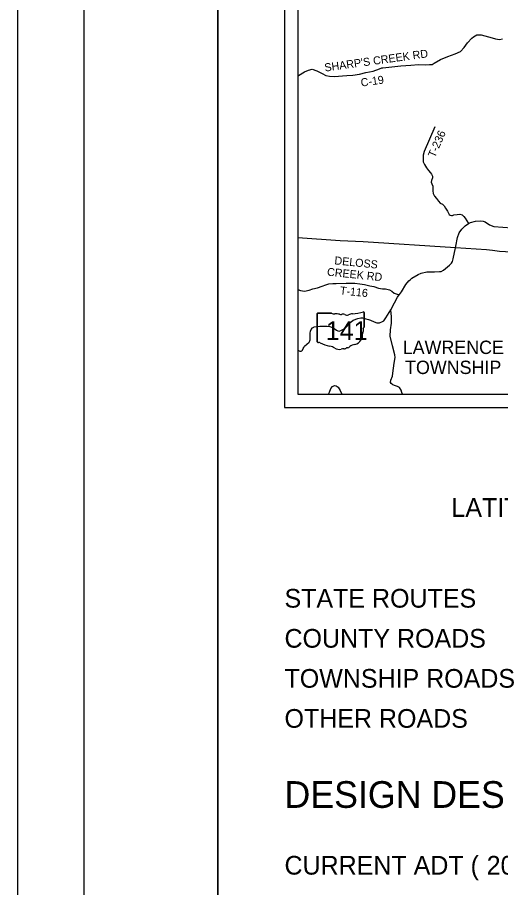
# Model space of a CAD drawing. Extents: x -6.4 to 34, y -1.2 to 22.
# Drawn here: x 0 to 3.62, y 10.4 to 16.92 of the extents above; entities that cross this region are included whole.
import ezdxf

# ---------------------------------------------------------------- set-up
doc = ezdxf.new("R2010")
doc.units = 0
for name, color, linetype in [('GM_X_County', 7, 'Continuous'), ('GM_X_County_ROW', 7, 'Continuous'), ('GM_X_Minor_Lake', 7, 'Continuous'), ('GM_X_Minor_River', 7, 'Continuous'), ('GM_X_Minor_River_Text', 7, 'Continuous'), ('GM_X_Section', 7, 'Continuous'), ('GM_X_Township', 7, 'Continuous'), ('GM_X_Township_Road', 7, 'Continuous'), ('GM_X_Township_ROW', 7, 'Continuous'), ('GM_X_Township_Subdivision', 7, 'Continuous'), ('GM_X_Township_Subdivision_Text', 7, 'Continuous'), ('GM_X_Township_Text', 7, 'Continuous')]:
    doc.layers.add(name, color=color, linetype=linetype)

msp = doc.modelspace()

# ---------------------------------------------------------------- linework, layer by layer
at = {"layer": 'GM_X_County'}
for points in [[(0.5, 21.5), (1.5, 21.5), (1.5, 0.5), (0.5, 0.5)], [(1.5, 21.5), (33.5, 21.5), (33.5, 0.5), (1.5, 0.5)]]:
    msp.add_lwpolyline(points, close=True, dxfattribs=at)
at = {"layer": 'GM_X_County_ROW'}
for p, q in [((2.2455, 14.7029), (2.2455, 14.4903)), ((2.3514, 14.7065), (2.2489, 14.7065)), ((2.5956, 14.6006), (2.5956, 14.7118)), ((2.5955, 14.6006), (2.5956, 14.6006))]:
    msp.add_line(p, q, dxfattribs=at)
for centre, major_axis, start_param, end_param in [((2.2495, 14.7033), (0.00406, 0), 1.712693, 3.28349), ((2.3759, 14.7312), (0.0393, 0), 4.042523, 4.731795), ((2.3889, 14.5872), (0.1412, 0), 1.404758, 1.657858), ((2.421, 14.7044), (0.0113, 0), 3.836095, 5.185415), ((2.4376, 14.6799), (0.0236, 0), 0.950623, 2.079405), ((2.4681, 14.7136), (0.0284, 0), 4.081561, 5.145723), ((2.5182, 14.6416), (0.0747, 0), 1.699011, 2.107814), ((2.4708, 14.9963), (0.3713, 0), 4.814394, 5.042369), ((2.5917, 14.7123), (0.0039, 0), 6.141152, 7.989035), ((2.4916, 14.5399), (0.0929, 0), 5.101752, 6.440018), ((2.6095, 14.5541), (0.0263, 0), 2.387724, 3.262537), ((2.5947, 14.5924), (0.00603, 0), 1.883978, 3.671073), ((2.5563, 14.5784), (0.0362, 0), 5.934695, 6.695948), ((2.5914, 14.6002), (0.00417, 0), 5.05454, 6.418171), ((2.2495, 14.4898), (0.00409, 0), 3.00124, 4.508301), ((2.2501, 14.5116), (0.0312, 0), 4.665946, 4.897461), ((2.2565, 14.478), (0.0113, 0), 0.519207, 1.627899), ((2.3987, 14.669), (0.2681, 0), 4.195997, 4.488961), ((2.3187, 14.3948), (0.0839, 0), 0.823519, 1.323587), ((2.4095, 14.477), (0.0532, 0), 4.026481, 4.996735), ((2.4402, 14.4035), (0.0437, 0), 1.495662, 1.94098), ((2.4441, 14.4611), (0.0284, 0), 4.691044, 5.507374), ((2.4698, 14.4405), (0.00798, 0), 1.147584, 2.315152), ((2.4664, 14.4697), (0.03, 0), 4.937069, 5.64225), ((2.5308, 14.4306), (0.0509, 0), 1.647645, 2.488434)]:
    msp.add_ellipse(centre, major_axis=major_axis, ratio=0.8, start_param=start_param, end_param=end_param, dxfattribs=at)
at = {"layer": 'GM_X_Minor_Lake'}
for points in [[(3.1163, 15.0159), (3.1195, 15.016), (3.1224, 15.0161), (3.16, 15.0171), (3.1737, 15.0188), (3.1901, 15.0273), (3.2345, 15.0644), (3.2498, 15.0801), (3.2571, 15.0918), (3.2627, 15.1137), (3.2794, 15.1952), (3.282, 15.208), (3.2961, 15.273), (3.309, 15.3078), (3.3291, 15.336), (3.3521, 15.3604), (3.3777, 15.3764), (3.3937, 15.3849), (3.4306, 15.3963), (3.4681, 15.3985), (3.487, 15.396), (3.5028, 15.3905), (3.5361, 15.3678), (3.5665, 15.3546), (3.7016, 15.3459)], [(2.9407, 14.9563), (2.9468, 14.9614), (2.9537, 14.9671), (3.0003, 14.9946), (3.0242, 15.005), (3.0656, 15.0144), (3.1163, 15.0159)], [(2.3199, 14.6094), (2.3383, 14.6058), (2.365, 14.5957), (2.3906, 14.5779), (2.4, 14.5729), (2.4083, 14.5705), (2.4209, 14.5753), (2.4312, 14.5813), (2.4548, 14.5943), (2.4629, 14.6018), (2.4813, 14.6235), (2.4989, 14.6412), (2.5138, 14.6524), (2.5489, 14.6649), (2.5728, 14.6707), (2.5849, 14.6717), (2.6098, 14.6646), (2.6283, 14.6587), (2.6449, 14.6528), (2.6709, 14.6415), (2.6913, 14.6333), (2.7106, 14.6342), (2.735, 14.6426), (2.743, 14.649), (2.7592, 14.672), (2.797, 14.7311), (2.8234, 14.7831), (2.8467, 14.8246), (2.8594, 14.8434), (2.8602, 14.8445), (2.8756, 14.8652), (2.9081, 14.9217), (2.9307, 14.948), (2.9407, 14.9563)], [(2.2199, 14.6018), (2.2227, 14.6034), (2.2648, 14.6086), (2.3194, 14.6095), (2.3199, 14.6094)], [(2.1, 14.4284), (2.1088, 14.4237), (2.1159, 14.4202), (2.1243, 14.4201), (2.1304, 14.4231), (2.135, 14.4295), (2.1404, 14.4408), (2.1439, 14.4499), (2.1505, 14.4585), (2.1846, 14.4892), (2.19, 14.4979), (2.1931, 14.507), (2.1933, 14.5218), (2.1918, 14.5552), (2.1943, 14.5718), (2.1993, 14.5839), (2.2086, 14.5956), (2.2199, 14.6018)]]:
    msp.add_lwpolyline(points, dxfattribs=at)
at = {"layer": 'GM_X_Minor_River'}
for points in [[(2.1, 16.4801), (2.106, 16.4873), (2.1497, 16.5143), (2.1801, 16.5264), (2.2075, 16.5328), (2.2428, 16.5218), (2.2826, 16.5009), (2.3096, 16.4872), (2.3373, 16.4804), (2.3723, 16.4796), (2.4661, 16.4864), (2.5109, 16.4887), (2.5618, 16.497), (2.6101, 16.5087), (2.6632, 16.5197), (2.7107, 16.5368), (2.7293, 16.5425), (2.7354, 16.5444), (2.7825, 16.5485), (2.8707, 16.5599), (2.9451, 16.564), (3.0036, 16.5697), (3.053, 16.5659), (3.0853, 16.5681), (3.1058, 16.5693), (3.1213, 16.5784), (3.1685, 16.6068), (3.2232, 16.6277), (3.2779, 16.6482), (3.3189, 16.6671), (3.3452, 16.6964), (3.3699, 16.7302), (3.4037, 16.7658), (3.4163, 16.7761), (3.4398, 16.7905), (3.4732, 16.7901), (3.5553, 16.7688), (3.5789, 16.7622), (3.5952, 16.7587), (3.6096, 16.7552), (3.6327, 16.76)], [(2.883, 14.1), (2.8799, 14.1104), (2.8743, 14.1301), (2.8606, 14.148), (2.8462, 14.1567), (2.8245, 14.1647), (2.812, 14.1689), (2.798, 14.178), (2.7949, 14.1856), (2.7968, 14.2042), (2.8094, 14.2327), (2.8121, 14.2555), (2.8216, 14.3303), (2.8277, 14.374), (2.8255, 14.3942), (2.8092, 14.4614), (2.791, 14.5343), (2.7926, 14.5807), (2.8006, 14.6312), (2.8014, 14.6794), (2.797, 14.7311)]]:
    msp.add_lwpolyline(points, dxfattribs=at)
at = {"layer": 'GM_X_Minor_River_Text'}
for points in [[(3.1247, 16.1013), (3.0448, 15.9165), (3.0391, 15.8896), (3.0375, 15.8592), (3.0379, 15.8391), (3.0478, 15.8189), (3.0633, 15.7954), (3.0796, 15.7749), (3.0933, 15.7574), (3.0997, 15.7471), (3.1081, 15.7316), (3.1092, 15.7202), (3.1016, 15.7004), (3.0982, 15.6875), (3.1042, 15.6754), (3.1099, 15.6575), (3.1114, 15.6233), (3.1125, 15.6032), (3.1224, 15.5835), (3.1383, 15.5645), (3.1535, 15.5447), (3.1668, 15.5295), (3.1841, 15.5221), (3.195, 15.511), (3.2045, 15.4934), (3.2199, 15.47), (3.2342, 15.446), (3.2411, 15.4412), (3.2516, 15.4371), (3.2584, 15.4383), (3.2681, 15.4425), (3.292, 15.4455), (3.3125, 15.4463), (3.33, 15.4421), (3.3437, 15.4299), (3.3524, 15.4182), (3.3777, 15.3764)], [(2.1, 14.8833), (2.1206, 14.8757), (2.1506, 14.8703), (2.1855, 14.879), (2.2125, 14.8874), (2.2475, 14.8965), (2.2816, 14.909), (2.309, 14.9192), (2.3322, 14.9257), (2.3626, 14.928), (2.3861, 14.9287), (2.4617, 14.9302), (2.4955, 14.9309), (2.5263, 14.9309), (2.5646, 14.9256), (2.5999, 14.9195), (2.6398, 14.9111), (2.6702, 14.9054), (2.7051, 14.894), (2.7344, 14.8894), (2.7553, 14.8879), (2.7864, 14.8799), (2.8031, 14.8712), (2.8221, 14.856), (2.8594, 14.8434)], [(2.3288, 14.1), (2.3368, 14.1148), (2.3467, 14.1421), (2.3589, 14.1565), (2.3733, 14.1645), (2.3862, 14.1626), (2.4025, 14.1512), (2.417, 14.1277), (2.4299, 14.1)]]:
    msp.add_lwpolyline(points, dxfattribs=at)
at = {"layer": 'GM_X_Section'}
msp.add_lwpolyline([(0, 0), (34, 0), (34, 22), (0, 22)], close=True, dxfattribs=at)
at = {"layer": 'GM_X_Township'}
for p, q in [((2, 21), (2, 14)), ((2.1, 20.9), (2.1, 14.1)), ((2.1, 14.1), (8.9, 14.1)), ((2, 14), (9, 14))]:
    msp.add_line(p, q, dxfattribs=at)
at = {"layer": 'GM_X_Township_Road'}
for p, q in [((2.2455, 14.4903), (2.2455, 14.7029)), ((2.2489, 14.7065), (2.3514, 14.7065)), ((2.5955, 14.7118), (2.5955, 14.6006)), ((2.5928, 14.597), (2.5928, 14.597))]:
    msp.add_line(p, q, dxfattribs=at)
for centre, major_axis, start_param, end_param in [((2.2495, 14.7033), (0.00406, 0), 1.712693, 3.28349), ((2.3759, 14.7312), (0.0393, 0), 4.042523, 4.731795), ((2.3889, 14.5872), (0.1412, 0), 1.404758, 1.657858), ((2.421, 14.7044), (0.0113, 0), 3.836095, 5.185415), ((2.4376, 14.6799), (0.0236, 0), 0.950623, 2.079405), ((2.4681, 14.7136), (0.0284, 0), 4.081561, 5.145723), ((2.5182, 14.6416), (0.0747, 0), 1.699011, 2.107814), ((2.4708, 14.9963), (0.3713, 0), 4.814394, 5.042369), ((2.5917, 14.7123), (0.0039, 0), 6.141152, 7.989035), ((2.4916, 14.5399), (0.0929, 0), 5.101752, 6.440018), ((2.6095, 14.5541), (0.0263, 0), 2.387724, 3.262537), ((2.5947, 14.5924), (0.00603, 0), 1.883978, 3.671073), ((2.5563, 14.5784), (0.0362, 0), 5.934695, 6.695948), ((2.5914, 14.6002), (0.00417, 0), 5.05454, 6.418171), ((2.2495, 14.4898), (0.00409, 0), 3.00124, 4.508301), ((2.2501, 14.5116), (0.0312, 0), 4.665946, 4.897461), ((2.2565, 14.478), (0.0113, 0), 0.519207, 1.627899), ((2.3987, 14.669), (0.2681, 0), 4.195997, 4.488961), ((2.3187, 14.3948), (0.0839, 0), 0.823519, 1.323587), ((2.4095, 14.477), (0.0532, 0), 4.026481, 4.996735), ((2.4402, 14.4035), (0.0437, 0), 1.495662, 1.94098), ((2.4441, 14.4611), (0.0284, 0), 4.691044, 5.507374), ((2.4698, 14.4405), (0.00798, 0), 1.147584, 2.315152), ((2.4664, 14.4697), (0.03, 0), 4.937069, 5.64225), ((2.5308, 14.4306), (0.0509, 0), 1.647645, 2.488434)]:
    msp.add_ellipse(centre, major_axis=major_axis, ratio=0.8, start_param=start_param, end_param=end_param, dxfattribs=at)
at = {"layer": 'GM_X_Township_ROW'}
msp.add_lwpolyline([(4.7383, 17.0951), (4.704, 16.5887), (4.6735, 16.1378), (4.6688, 16.1067), (4.6617, 15.9964), (4.6068, 15.1539), (4.6039, 15.1106), (4.4494, 15.1194), (4.2374, 15.1315), (3.9258, 15.1493), (3.6093, 15.1673), (3.5571, 15.1752), (3.5118, 15.1797), (3.2794, 15.1952), (2.59, 15.2415), (2.4159, 15.2489), (2.1, 15.2699)], dxfattribs=at)

# ---------------------------------------------------------------- texts
at = {"layer": 'GM_X_County_ROW'}
msp.add_text('141', height=0.14004, dxfattribs=at).set_placement((2.3094, 14.5053))
at = {"layer": 'GM_X_Township'}
for s, height, p in [('LATITUDE:  38°38\'06"     LONGITUDE:  82°27\'51"', 0.14, (3.25, 13.18)), ('STATE ROUTES', 0.14, (2, 12.5)), ('COUNTY ROADS', 0.14, (2, 12.2)), ('TOWNSHIP ROADS', 0.14, (2, 11.9)), ('OTHER ROADS', 0.14, (2, 11.6)), ('DESIGN DESIGNATION', 0.2, (2, 11)), ('CURRENT ADT (', 0.14, (2, 10.5)), ('2018', 0.14, (3.5142, 10.5))]:
    msp.add_text(s, height=height, dxfattribs=at).set_placement(p)
at = {"layer": 'GM_X_Township_Subdivision'}
for s, rotation, p in [('T-236', 66.62912, (3.1265, 15.8662)), ('DELOSS', 354.24587, (2.3718, 15.0721)), ('CREEK RD', 354.24587, (2.3165, 14.9872)), ('T-116', 354.24587, (2.4128, 14.8469))]:
    msp.add_text(s, height=0.06, rotation=rotation, dxfattribs=at).set_placement(p)
at = {"layer": 'GM_X_Township_Subdivision_Text'}
for s, p in [('LAWRENCE', (2.8854, 14.4)), ('TOWNSHIP', (2.9028, 14.25))]:
    msp.add_text(s, height=0.1, dxfattribs=at).set_placement(p)
at = {"layer": 'GM_X_Township_Text'}
for s, p in [("SHARP'S CREEK RD", (2.3034, 16.5154)), ('C-19', (2.5749, 16.4029))]:
    msp.add_text(s, height=0.06, rotation=7.92776, dxfattribs=at).set_placement(p)

doc.saveas('drawing.dxf')
